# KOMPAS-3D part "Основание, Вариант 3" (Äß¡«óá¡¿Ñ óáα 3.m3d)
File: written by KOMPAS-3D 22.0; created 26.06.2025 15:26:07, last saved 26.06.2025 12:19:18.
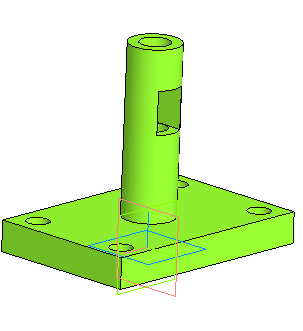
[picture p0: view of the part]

Document properties: Автор: Helen; Полное имя файла: D:\MY\WORK\MPEI\ППЭ_2025-2026\Варианты\Вар 3 СБ\Основание вар 3.m3d

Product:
- Body: Тело 1
    Масса: 2.245738
- Part/product: Основание  | designation Вариант 3
    Масса: 2.63815

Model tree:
1. Эскиз:1
2. Элемент выдавливания:1
     Расстояние 1 = 20
3. Эскиз:3  (with: Элемент выдавливания:1)
4. Элемент выдавливания:3
     Расстояние 2 = 20
5. Массив по сетке:1  (with: Элемент выдавливания:3, Эскиз:3, Элемент выдавливания:1)  (4 pattern instances)
     Шаг 1 = 120; Угол раствора = 90; Шаг 2 = 70
6. Эскиз:4  (with: Элемент выдавливания:1)
7. Элемент выдавливания:4
     Расстояние 1 = 110
8. Эскиз:5  (with: Элемент выдавливания:4)
9. Элемент выдавливания:5
     Расстояние 2 = 130
10. Эскиз:6
11. Элемент выдавливания:6
     Расстояние 1 = 50

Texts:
  Вариант 3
